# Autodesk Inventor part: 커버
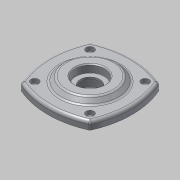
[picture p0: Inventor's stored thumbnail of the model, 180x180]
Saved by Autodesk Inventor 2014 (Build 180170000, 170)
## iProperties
Created: 2016-05
Part Number: 커버
Document SubType Name: Modeling
Designer: mduedu
Density: 2.71 g/cm^3
Material: 알루미늄 6061
Appearance: 알루미늄 - 평지
Author: mduedu
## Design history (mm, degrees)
sketch "스케치1"
  geometry: L1 (0, 0)-(-35.355, 35.355); L2 (0, 0)-(0, 43); L3 (0, 0)-(43, 0); C1 r 25 at (0, 0); A1 r 85.579 centre (0, -42.579) between (35.355, 35.355) and (-35.355, 35.355); A2 r 85.579 centre (42.579, 0) between (-35.355, 35.355) and (-35.355, -35.355); A3 r 85.579 centre (0, 42.579) between (-35.355, -35.355) and (35.355, -35.355); A4 r 85.579 centre (-42.579, 0) between (35.355, -35.355) and (35.355, 35.355); 1 further point
  constraints: 10 point on circle, 6 end point, 5 centre point, 2 horizontal alignment, 2 vertical alignment, 1 coincident, 1 equal radius, 2 other
  dimensions: "d28" = 86 dimension on A4 A2; "d30" = 50 diameter of C1; "d31" = 45 deg angle of L2 L1; "d32" = 100 distance of A3.end L1.end
extrude "돌출1" new body sketch "스케치1" distance "d0" = 8; taper "d1" = 0 deg
extrude "돌출2" join sketch "스케치1" distance "d2" = 12; taper "d3" = 0 deg
sketch "스케치2"
  geometry: C1 r 30 at (0, 0); 1 further point
  constraints: 1 centre point, 1 coincident
  dimensions: "d4" = 60 diameter of C1
extrude "돌출3" join sketch "스케치2" distance "d5" = 5; taper "d6" = -45 deg
sketch "스케치3"
  geometry: C1 r 1.621 at (-28.284, 28.284) reference; C2 r 1.621 at (28.284, 28.284) reference; C3 r 1.621 at (28.284, -28.284) reference; C4 r 1.621 at (-28.284, -28.284) reference; 1 further point
hole "구멍1" sketch "스케치3" at (28.284, 28.284), (-28.284, 28.284), (-28.284, -28.284), (28.284, -28.284) diameter "d7" = 4.5; stored, may be unused: countersink angle "d11" = 90 deg, drill point angle "d13" = 118 deg; dims "d8" = 6, "d9" = 8, "d10" = 4.4, "d12" = 8
fillet "모깎기1" dims "d14" = 3
sketch "스케치4"
  geometry: L1 (-23.757, 13)-(23.757, 13) reference; L2 (25, -12)-(-25, -12) reference; L3 (0, -12)-(0, 13); L4 (-20, -12)-(-20, 0); L5 (-20, 0)-(-15, 0); L6 (-15, 0)-(-15, 3); L7 (-15, 3)-(-10, 3); L8 (-10, 3)-(-10, 5); L9 (-10, 5)-(-15, 5); L10 (-15, 5)-(-15, 13); 1 further point
  constraints: 16 end point, 6 parallel, 2 midpoint, 2 point on line, 1 perpendicular
  dimensions: "d15" = 40 diameter of L4 L3; "d16" = 30 diameter of L10 L3; "d17" = 8 distance of L9.end L10.end; "d18" = 12 distance of L4.start L4.end; "d19" = 3 distance of L5.end L6.end; "d20" = 30 diameter of L6 L3; "d21" = 20 diameter of L8 L3
revolve "회전1" sketch "스케치4" stored, may be unused: angle "d22" = 90 deg
fillet "모깎기2" dims "d23" = 3
fillet "모깎기3" dims "d24" = 0.3
chamfer "모따기1" distance "d25" = 1; stored, may be unused: second distance "d26" = 2, angle "d27" = 45 deg
node "솔리드1"
node "참조2"
node "참조3"
node "참조4"
node "참조5"
